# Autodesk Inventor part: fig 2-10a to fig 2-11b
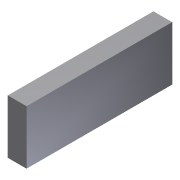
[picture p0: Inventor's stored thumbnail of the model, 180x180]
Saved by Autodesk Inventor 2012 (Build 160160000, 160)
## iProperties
Created: 2011-06
Part Number: fig 2-10a to fig 2-11b
Material: Default
Document SubType Name: Modeling
Designer: CadCim
Density: 1 g/cm^3
Author: CadCim
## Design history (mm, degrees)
sketch "Sketch1"
  geometry: 1 further point
sketch "Sketch2"
  geometry: L1 (-35, 13)-(0, 13); L2 (0, 13)-(0, 0); L3 (0, 0)-(-35, 0); L4 (-35, 0)-(-35, 13); 1 further point
  constraints: 8 end point, 2 parallel, 1 coincident, 1 horizontal, 1 perpendicular
extrude "Extrusion1" new body sketch "Sketch2" distance "d0" = 4.5; taper "d1" = 0 deg
body "Solid1"
